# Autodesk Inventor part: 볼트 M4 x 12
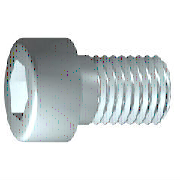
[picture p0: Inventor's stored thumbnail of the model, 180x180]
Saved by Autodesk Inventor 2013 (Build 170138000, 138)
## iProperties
IsCustomPart: 0
Created: 2012-02
Part Number: 볼트 M4 x 12
Material: 스테인리스강
Description: 6각 소켓 머리 캡 나사
Document SubType Name: Modeling
Standard: ISO 4762
Designer: mduedu
Standard Revision: Fourth edition 2004-03-01
Standards Organization: ISO
Language: ko-KR
Size Designation: M4 x 12
Categories: <MemberInstance><Categories><Category DisplayName="조임쇠" InternalName="e4da775c-781d-43d5-af7c-5136215cf5a6" Mnemonic="FSTN"><Category DisplayName="볼트" InternalN
Density: 8.08 g/cm^3
Author: mduedu
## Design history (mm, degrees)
sketch "스케치1"
  geometry: L1 (-1, 0)-(12, 0); L2 (12, 0)-(12, 2); L3 (12, 2)-(1.75, 2); L4 (1.75, 2)-(1.32, 2); L5 (1.32, 2)-(0, 2); L6 (0, 2)-(0, 3.5); L7 (0, 3.5)-(-4, 3.5); L8 (-4, 3.5)-(-4, 1.732); L9 (-4, 1.732)-(-2, 1.732); L10 (-2, 1.732)-(-1, 0); L11 (-7.2, 0)-(15.2, 0) reference; L12 (0, -0.7)-(0, 4.2) reference; L13 (1.75, 2)-(0, 2)
  constraints: 22 end point, 6 parallel, 2 collinear, 2 perpendicular, 1 horizontal, 1 point on line
  dimensions: "d1" = 10.25 distance from line of L3.end L2 (= GEL); "d2" = 0.42952 distance of L4.end L3.end (computed from GAL); "d3" = 4 distance between parallel lines of L8 L6 (= KOH); "d4" = 2 distance of L8.end L9.end (= INTI); "d5" = 60 deg angle of L10 L1; "d6" = 4 diameter of L3 L1 (= GD); "d7" = 4 diameter of L5 L1 (= BDM); "d8" = 3.4641 diameter of L9 L1 (= 1.1547 x SW); "d9" = 7 diameter of L7 L1 (= KOD); "d26" = 12 distance between parallel lines of L12 L2 (= NLG)
revolve "본체" sketch "스케치1" stored, may be unused: angle "d10" = 90 deg
sketch "스케치2"
  geometry: L1 (0, -4.9)-(0, 4.9) reference; L2 (-4.9, 0)-(4.9, 0) reference; L3 (1.732, 0)-(0.866, -1.5); L4 (0.866, -1.5)-(-0.866, -1.5); L5 (-0.866, -1.5)-(-1.732, 0); L6 (-1.732, 0)-(-0.866, 1.5); L7 (-0.866, 1.5)-(0.866, 1.5); L8 (0.866, 1.5)-(1.732, 0); 2 further points
  constraints: 12 end point, 1 coincident, 1 horizontal alignment, 1 point on line, 12 other
extrude "슬롯" join sketch "스케치2" stored distance "d11" = 10; taper "d12" = 0 deg
workplane "Work Plane1"
fillet "Fillet2" dims "d30" = 0.1 (= R)
body "Solid1"
fillet "모깎기1" dims "d17" = 0.4 (= RR)
feature "스레드" dims "d13" = 10.25 (= GEL), "d14" = 0
chamfer "모따기1" distance "d15" = 0.42941 (= -0.5 x SPD + 0.5 x GD); stored, may be unused: second distance "d16" = 0.42941 (= GUL), angle "d27" = 45 deg
other parameters: "GD" = 4 [user parameter; used in 2 equation terms], "NLG" = 12 [user parameter; used in 1 equation term], "GEL" = 10.25 [user parameter; used in 2 equation terms], "KOD" = 7 [user parameter; used in 1 equation term], "KOH" = 4 [user parameter; used in 1 equation term], "INTI" = 2 [user parameter; used in 1 equation term], "GAL" = 0.42941 (= 0.61345 x PTC) [user parameter; used in 1 equation term], "GUL" = 0.42941 (= 0.61345 x PTC) [user parameter; used in 1 equation term], "BDM" = 4 (= NND) [user parameter; used in 1 equation term], "SW" = 3 [user parameter; used in 2 equation terms], "RR" = 0.4 [user parameter; used in 1 equation term], "SPD" = 3.14117 (= NND - 1.2269 x PTC) [user parameter; used in 1 equation term], "d19" = 0, "d28" = 0, "d29" = 0, "R" = 0.1 [user parameter; used in 1 equation term], "TOA" = 30 deg [user parameter], "GD1" = 3.14117 (= THREADDIA - 1.2269 x PTC) [user parameter], "THREADDIA" = 4 [user parameter; used in 1 equation term], "FAWI" = 45 deg [user parameter], "TPU" = 14.28571 (computed from PTC) [user parameter], "PTC" = 0.7 [user parameter; used in 5 equation terms], "NND" = 4 [user parameter; used in 2 equation terms], "E0" = 3.465 (= 1.155 x SW) [user parameter]
